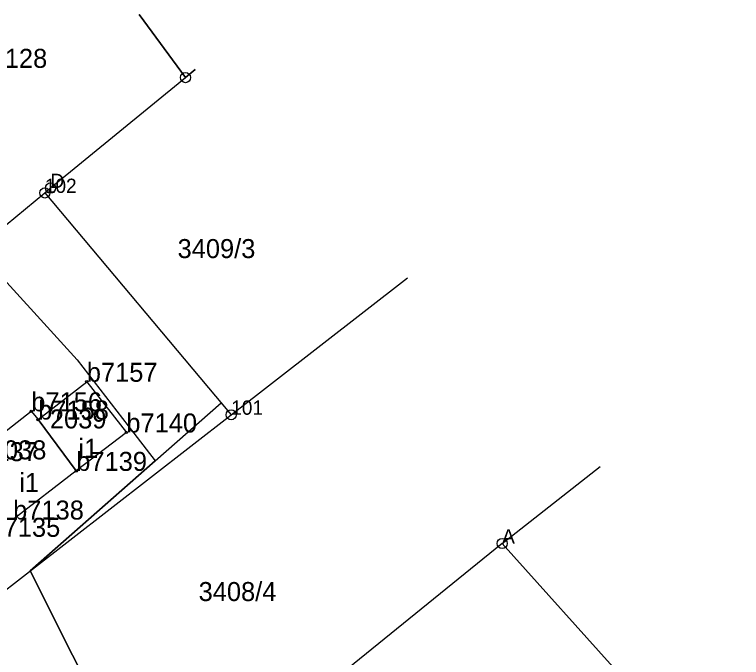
# Model space of a CAD drawing. Extents: x 7492083 to 7492670, y 5466693 to 5467065.
# Drawn here: x 7492261.9 to 7492319.2, y 5466933.4 to 5466984.1 of the extents above; entities that cross this region are included whole.
import ezdxf

# ---------------------------------------------------------------- set-up
doc = ezdxf.new("R2010")
doc.units = 0
for name, color, linetype in [('202-punkt graniczny', 7, 'Continuous'), ('202-punkt graniczny-Atr103', 7, 'Continuous'), ('211-numer działki ewidencyjnej', 7, 'Continuous'), ('217-kontur klasyfikacyjny', 7, 'Continuous'), ('218-kontur użytku gruntowego', 7, 'Continuous'), ('219-działka ewidencyjna', 7, 'Continuous'), ('312-budynek ewidencyjny', 7, 'Continuous'), ('312-oznaczenie budynku ewidencyjnego', 7, 'Continuous'), ('312-oznaczenie budynku ewidencyjnego-Atr117', 7, 'Continuous'), ('Punkt budynku', 7, 'Continuous'), ('Punkt budynku-Atr103', 7, 'Continuous')]:
    doc.layers.add(name, color=color, linetype=linetype)

# ---------------------------------------------------------------- blocks, each defined once
blk = doc.blocks.new('202')
blk.add_circle((0, 0), 0.4)
blk = doc.blocks.new('PUNKTBUD')
blk.add_circle((0, 0), 0.09)

msp = doc.modelspace()

# ---------------------------------------------------------------- linework, layer by layer
at = {"layer": '217-kontur klasyfikacyjny'}
for points in [[(7492275.34, 5466979.16), (7492271.679, 5466984.136)], [(7492276.112, 5466979.79), (7492275.34, 5466979.16)], [(7492258.85, 5466965.61), (7492266.79, 5466956.88)], [(7492278.95, 5466952.56), (7492292.863, 5466963.372)], [(7492266.79, 5466956.88), (7492270.82, 5466951.68)], [(7492272.96, 5466948.93), (7492278.15, 5466953.51)], [(7492278.15, 5466953.51), (7492278.95, 5466952.56)], [(7492270.82, 5466951.68), (7492272.96, 5466948.93)], [(7492272.96, 5466948.93), (7492263.09, 5466940.24)], [(7492263.09, 5466940.24), (7492273.09, 5466920.33)]]:
    msp.add_lwpolyline(points, dxfattribs=at)
at = {"layer": '218-kontur użytku gruntowego'}
for points in [[(7492275.34, 5466979.16), (7492271.679, 5466984.136)], [(7492276.112, 5466979.79), (7492275.34, 5466979.16)], [(7492258.85, 5466965.61), (7492266.79, 5466956.88)], [(7492278.95, 5466952.56), (7492292.863, 5466963.372)], [(7492266.79, 5466956.88), (7492270.82, 5466951.68)], [(7492272.96, 5466948.93), (7492278.15, 5466953.51)], [(7492278.15, 5466953.51), (7492278.95, 5466952.56)], [(7492270.82, 5466951.68), (7492272.96, 5466948.93)], [(7492263.09, 5466940.24), (7492272.96, 5466948.93)], [(7492273.09, 5466920.33), (7492263.09, 5466940.24)]]:
    msp.add_lwpolyline(points, dxfattribs=at)
at = {"layer": '219-działka ewidencyjna'}
for points in [[(7492271.679, 5466984.136), (7492275.34, 5466979.16)], [(7492275.34, 5466979.16), (7492276.113, 5466979.789)], [(7492264.69, 5466970.45), (7492275.34, 5466979.16)], [(7492264.25, 5466970.06), (7492264.69, 5466970.45)], [(7492258.13, 5466965.01), (7492264.25, 5466970.06)], [(7492264.25, 5466970.06), (7492278.95, 5466952.56)], [(7492278.95, 5466952.56), (7492292.866, 5466963.369)], [(7492237.56, 5466920.41), (7492278.95, 5466952.56)], [(7492300.32, 5466942.4), (7492308.048, 5466948.489)], [(7492300.32, 5466942.4), (7492278.38, 5466924.61)], [(7492300.32, 5466942.4), (7492319.2, 5466921.35)]]:
    msp.add_lwpolyline(points, dxfattribs=at)
at = {"layer": '312-budynek ewidencyjny'}
for points in [[(7492263.72, 5466952.18), (7492267.56, 5466955.16)], [(7492267.56, 5466955.16), (7492270.68, 5466951.16)], [(7492258.12, 5466948.9), (7492263.18, 5466952.83)], [(7492263.18, 5466952.83), (7492263.72, 5466952.18)], [(7492263.72, 5466952.18), (7492266.73, 5466948.13)], [(7492266.73, 5466948.13), (7492263.72, 5466952.18)], [(7492270.68, 5466951.16), (7492266.73, 5466948.13)], [(7492266.73, 5466948.13), (7492261.75, 5466944.29)]]:
    msp.add_lwpolyline(points, dxfattribs=at)

# ---------------------------------------------------------------- block references
at = {"layer": '202-punkt graniczny'}
for p in [(7492275.34, 5466979.16), (7492264.69, 5466970.45), (7492264.25, 5466970.06), (7492278.95, 5466952.56), (7492300.32, 5466942.4)]:
    msp.add_blockref('202', p, dxfattribs=at)
at = {"layer": 'Punkt budynku'}
for p in [(7492267.56, 5466955.16), (7492263.18, 5466952.83), (7492263.72, 5466952.18), (7492270.68, 5466951.16), (7492266.73, 5466948.13)]:
    msp.add_blockref('PUNKTBUD', p, dxfattribs=at)

# ---------------------------------------------------------------- texts
at = {"layer": '202-punkt graniczny-Atr103'}
for s, p in [('D', (7492264.69, 5466970.45)), ('102', (7492264.25, 5466970.06)), ('101', (7492278.95, 5466952.56)), ('A', (7492300.32, 5466942.4))]:
    msp.add_text(s, height=1.125, dxfattribs=at).set_placement(p)
at = {"layer": '211-numer działki ewidencyjnej'}
for s, p in [('3409/3', (7492274.72, 5466964.92)), ('3408/4', (7492276.38, 5466937.86))]:
    msp.add_text(s, height=1.5, dxfattribs=at).set_placement(p)
at = {"layer": '312-oznaczenie budynku ewidencyjnego'}
for s, p in [('2039', (7492264.65, 5466951.48)), ('2038', (7492259.91, 5466949.04))]:
    msp.add_text(s, height=1.5, dxfattribs=at).set_placement(p)
at = {"layer": '312-oznaczenie budynku ewidencyjnego-Atr117'}
for p in [(7492266.9, 5466949.16), (7492262.23, 5466946.46)]:
    msp.add_text('i1', height=1.5, dxfattribs=at).set_placement(p)
at = {"layer": 'Punkt budynku-Atr103'}
for s, p in [('b7128', (7492258.86, 5466979.93)), ('b7157', (7492267.56, 5466955.16)), ('b7156', (7492263.18, 5466952.83)), ('b7158', (7492263.72, 5466952.18)), ('b7140', (7492270.68, 5466951.16)), ('b7137', (7492258.12, 5466948.9)), ('b7139', (7492266.73, 5466948.13)), ('b7138', (7492261.75, 5466944.29)), ('b7135', (7492259.89, 5466942.93))]:
    msp.add_text(s, height=1.5, dxfattribs=at).set_placement(p)

doc.saveas('drawing.dxf')
